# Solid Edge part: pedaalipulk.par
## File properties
Author: Türk
Template: Iso Part.par
Last saved by: Türk
Revision: 6
Application: Solid Edge
Accuracy: 0,990
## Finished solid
Body 1: solid body, 7 faces, 6 edges, 0 vertices.
  Faces by surface: plane 4, cylinder 3
  Edges by curve: circle 6
Bounding box of the edges (mm): 35.000 x 180.000 x 35.000, from (-17.5, -2, -17.5) to (17.5, 178, 17.5).
Cylindrical faces by radius (mm): R10 x1, R17.5 x2
Planar faces by outward normal: +y 2, -y 2
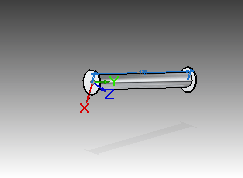
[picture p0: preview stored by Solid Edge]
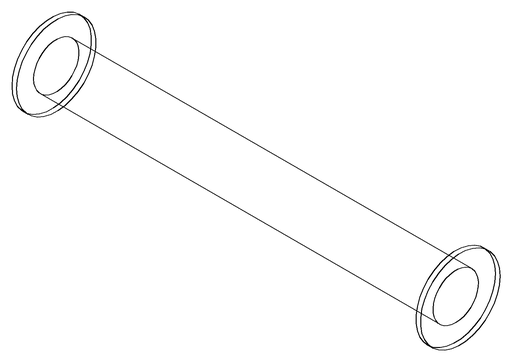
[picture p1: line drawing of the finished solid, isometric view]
